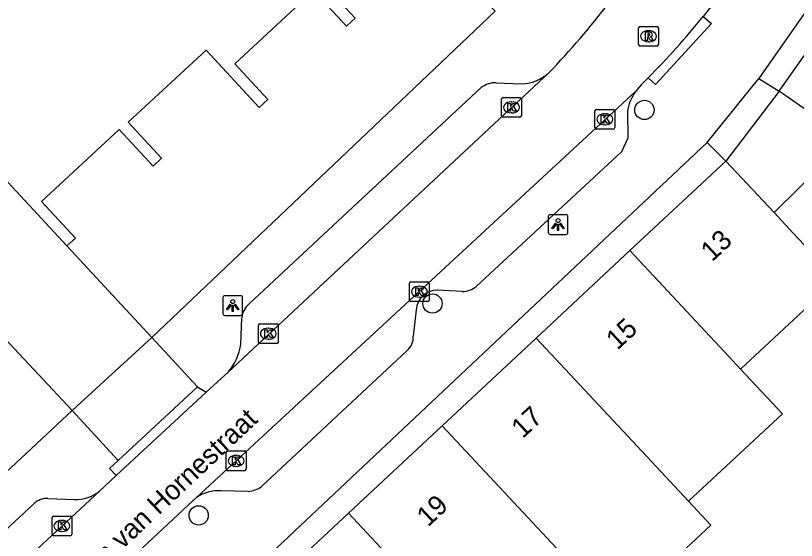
# Model space of a CAD drawing. Extents: x 161801 to 162379, y 382315 to 382832.
# Drawn here: x 161918.18 to 161957.74, y 382686.7 to 382713.31 of the extents above; entities that cross this region are included whole.
import ezdxf

# ---------------------------------------------------------------- set-up
doc = ezdxf.new("R2010")
doc.units = 0
for name, color, linetype in [('IMGEO_Boom', 7, 'Continuous'), ('IMGEO_Kolk', 7, 'Continuous'), ('IMGEO_Lichtpunt', 7, 'Continuous'), ('IMGEO_Openbare_ruimte_label', 7, 'Continuous'), ('IMGEO_Pand', 7, 'Continuous'), ('IMGEO_Pand_nummerreeks', 7, 'Continuous'), ('IMGEO_Pand_overbouw', 7, 'Continuous'), ('IMGEO_Rijbaan_lokaal_open', 7, 'Continuous'), ('IMGEO_Rioolput', 7, 'Continuous'), ('IMGEO_Voetpad_open', 7, 'Continuous')]:
    doc.layers.add(name, color=color, linetype=linetype)

msp = doc.modelspace()

# ---------------------------------------------------------------- linework, layer by layer
at = {"layer": 'IMGEO_Boom'}
for centre in [(161950.038, 382708.52), (161939.3, 382698.705), (161927.456, 382687.964)]:
    msp.add_circle(centre, 0.489, dxfattribs=at)
at = {"layer": 'IMGEO_Kolk'}
for p, q in [((161942.805, 382708.227), (161942.805, 382709.079)), ((161942.88, 382709.153), (161943.732, 382709.153)), ((161943.806, 382709.079), (161943.806, 382708.227)), ((161943.293, 382708.933), (161943.318, 382708.933)), ((161943.316, 382708.373), (161943.291, 382708.373)), ((161947.532, 382707.624), (161947.532, 382708.476)), ((161947.607, 382708.55), (161948.459, 382708.55)), ((161948.02, 382708.33), (161948.045, 382708.33)), ((161948.533, 382708.476), (161948.533, 382707.624)), ((161943.732, 382708.153), (161942.88, 382708.153)), ((161948.459, 382707.55), (161947.607, 382707.55)), ((161948.043, 382707.77), (161948.018, 382707.77)), ((161938.135, 382698.881), (161938.135, 382699.733)), ((161938.21, 382699.807), (161939.062, 382699.807)), ((161938.623, 382699.587), (161938.648, 382699.587)), ((161939.136, 382699.733), (161939.136, 382698.881)), ((161939.062, 382698.807), (161938.21, 382698.807)), ((161938.646, 382699.027), (161938.621, 382699.027)), ((161930.558, 382697.677), (161931.41, 382697.677)), ((161930.483, 382696.751), (161930.483, 382697.603)), ((161930.971, 382697.457), (161930.996, 382697.457)), ((161931.484, 382697.603), (161931.484, 382696.751)), ((161930.994, 382696.897), (161930.969, 382696.897)), ((161931.41, 382696.677), (161930.558, 382696.677)), ((161928.854, 382690.303), (161928.854, 382691.155)), ((161928.929, 382691.229), (161929.781, 382691.229)), ((161929.342, 382691.009), (161929.367, 382691.009)), ((161929.855, 382691.155), (161929.855, 382690.303)), ((161929.781, 382690.229), (161928.929, 382690.229)), ((161929.365, 382690.449), (161929.34, 382690.449)), ((161920.026, 382687.006), (161920.026, 382687.858)), ((161920.101, 382687.932), (161920.953, 382687.932)), ((161921.027, 382687.858), (161921.027, 382687.006)), ((161920.514, 382687.712), (161920.539, 382687.712)), ((161920.953, 382686.932), (161920.101, 382686.932)), ((161920.537, 382687.152), (161920.512, 382687.152))]:
    msp.add_line(p, q, dxfattribs=at)
for points in [[(161942.805, 382708.227), (161942.805, 382709.079)], [(161942.88, 382709.153), (161943.732, 382709.153)], [(161943.806, 382709.079), (161943.806, 382708.227)], [(161943.126, 382708.853), (161943.249, 382708.853), (161943.249, 382708.702), (161943.379, 382708.853), (161943.543, 382708.853), (161943.397, 382708.702), (161943.55, 382708.453), (161943.398, 382708.453), (161943.313, 382708.617), (161943.249, 382708.55), (161943.249, 382708.453), (161943.126, 382708.453), (161943.126, 382708.853)], [(161947.532, 382707.624), (161947.532, 382708.476)], [(161947.607, 382708.55), (161948.459, 382708.55)], [(161948.533, 382708.476), (161948.533, 382707.624)], [(161943.732, 382708.153), (161942.88, 382708.153)], [(161947.853, 382708.25), (161947.976, 382708.25), (161947.976, 382708.099), (161948.106, 382708.25), (161948.27, 382708.25), (161948.124, 382708.099), (161948.277, 382707.85), (161948.125, 382707.85), (161948.04, 382708.014), (161947.976, 382707.947), (161947.976, 382707.85), (161947.853, 382707.85), (161947.853, 382708.25)], [(161948.459, 382707.55), (161947.607, 382707.55)], [(161938.135, 382698.881), (161938.135, 382699.733)], [(161938.21, 382699.807), (161939.062, 382699.807)], [(161939.136, 382699.733), (161939.136, 382698.881)], [(161938.456, 382699.507), (161938.579, 382699.507), (161938.579, 382699.356), (161938.709, 382699.507), (161938.873, 382699.507), (161938.727, 382699.356), (161938.88, 382699.107), (161938.728, 382699.107), (161938.643, 382699.271), (161938.579, 382699.204), (161938.579, 382699.107), (161938.456, 382699.107), (161938.456, 382699.507)], [(161939.062, 382698.807), (161938.21, 382698.807)], [(161930.558, 382697.677), (161931.41, 382697.677)], [(161930.483, 382696.751), (161930.483, 382697.603)], [(161930.804, 382697.377), (161930.927, 382697.377), (161930.927, 382697.226), (161931.057, 382697.377), (161931.221, 382697.377), (161931.075, 382697.226), (161931.228, 382696.977), (161931.076, 382696.977), (161930.991, 382697.141), (161930.927, 382697.074), (161930.927, 382696.977), (161930.804, 382696.977), (161930.804, 382697.377)], [(161931.484, 382697.603), (161931.484, 382696.751)], [(161931.41, 382696.677), (161930.558, 382696.677)], [(161928.854, 382690.303), (161928.854, 382691.155)], [(161928.929, 382691.229), (161929.781, 382691.229)], [(161929.175, 382690.929), (161929.298, 382690.929), (161929.298, 382690.778), (161929.428, 382690.929), (161929.592, 382690.929), (161929.446, 382690.778), (161929.599, 382690.529), (161929.447, 382690.529), (161929.362, 382690.693), (161929.298, 382690.626), (161929.298, 382690.529), (161929.175, 382690.529), (161929.175, 382690.929)], [(161929.855, 382691.155), (161929.855, 382690.303)], [(161929.781, 382690.229), (161928.929, 382690.229)], [(161920.026, 382687.006), (161920.026, 382687.858)], [(161920.101, 382687.932), (161920.953, 382687.932)], [(161921.027, 382687.858), (161921.027, 382687.006)], [(161920.347, 382687.632), (161920.47, 382687.632), (161920.47, 382687.481), (161920.6, 382687.632), (161920.764, 382687.632), (161920.618, 382687.481), (161920.771, 382687.232), (161920.619, 382687.232), (161920.534, 382687.396), (161920.47, 382687.329), (161920.47, 382687.232), (161920.347, 382687.232), (161920.347, 382687.632)], [(161920.953, 382686.932), (161920.101, 382686.932)]]:
    msp.add_lwpolyline(points, dxfattribs=at)
for centre, start, end in [((161942.882, 382709.077), 91.552, 178.448), ((161942.882, 382709.077), 91.552, 178.448), ((161943.73, 382709.077), 1.552, 88.448), ((161943.73, 382709.077), 1.552, 88.448), ((161947.609, 382708.474), 91.552, 178.448), ((161947.609, 382708.474), 91.552, 178.448), ((161948.457, 382708.474), 1.552, 88.448), ((161948.457, 382708.474), 1.552, 88.448), ((161942.882, 382708.229), 181.552, 268.448), ((161942.882, 382708.229), 181.552, 268.448), ((161943.73, 382708.229), 271.552, 358.448), ((161943.73, 382708.229), 271.552, 358.448), ((161947.609, 382707.626), 181.552, 268.448), ((161947.609, 382707.626), 181.552, 268.448), ((161948.457, 382707.626), 271.552, 358.448), ((161948.457, 382707.626), 271.552, 358.448), ((161938.212, 382699.731), 91.552, 178.448), ((161938.212, 382699.731), 91.552, 178.448), ((161939.06, 382699.731), 1.552, 88.448), ((161939.06, 382699.731), 1.552, 88.448), ((161938.212, 382698.883), 181.552, 268.448), ((161938.212, 382698.883), 181.552, 268.448), ((161939.06, 382698.883), 271.552, 358.448), ((161939.06, 382698.883), 271.552, 358.448), ((161930.56, 382697.601), 91.552, 178.448), ((161930.56, 382697.601), 91.552, 178.448), ((161931.408, 382697.601), 1.552, 88.448), ((161931.408, 382697.601), 1.552, 88.448), ((161930.56, 382696.753), 181.552, 268.448), ((161930.56, 382696.753), 181.552, 268.448), ((161931.408, 382696.753), 271.552, 358.448), ((161931.408, 382696.753), 271.552, 358.448), ((161928.931, 382691.153), 91.552, 178.448), ((161928.931, 382691.153), 91.552, 178.448), ((161929.779, 382691.153), 1.552, 88.448), ((161929.779, 382691.153), 1.552, 88.448), ((161928.931, 382690.305), 181.552, 268.448), ((161928.931, 382690.305), 181.552, 268.448), ((161929.779, 382690.305), 271.552, 358.448), ((161929.779, 382690.305), 271.552, 358.448), ((161920.103, 382687.856), 91.552, 178.448), ((161920.103, 382687.856), 91.552, 178.448), ((161920.951, 382687.856), 1.552, 88.448), ((161920.951, 382687.856), 1.552, 88.448), ((161920.103, 382687.008), 181.552, 268.448), ((161920.103, 382687.008), 181.552, 268.448), ((161920.951, 382687.008), 271.552, 358.448), ((161920.951, 382687.008), 271.552, 358.448)]:
    msp.add_arc(centre, 0.0765, start, end, dxfattribs=at)
for centre, major_axis, ratio, start_param, end_param in [((161943.292, 382708.653), (-0.387, 0.002), 0.722429, 4.712389, 7.853982), ((161943.317, 382708.653), (-0.39, 0.002), 0.717154, 1.570796, 4.712389), ((161948.019, 382708.05), (-0.387, 0.002), 0.722429, 4.712389, 7.853982), ((161948.044, 382708.05), (-0.39, 0.002), 0.717154, 1.570796, 4.712389), ((161938.622, 382699.307), (-0.387, 0.002), 0.722429, 4.712389, 7.853982), ((161938.647, 382699.307), (-0.39, 0.002), 0.717154, 1.570796, 4.712389), ((161930.97, 382697.177), (-0.387, 0.002), 0.722429, 4.712389, 7.853982), ((161930.995, 382697.177), (-0.39, 0.002), 0.717154, 1.570796, 4.712389), ((161929.341, 382690.729), (-0.387, 0.002), 0.722429, 4.712389, 7.853982), ((161929.366, 382690.729), (-0.39, 0.002), 0.717154, 1.570796, 4.712389), ((161920.513, 382687.432), (-0.387, 0.002), 0.722429, 4.712389, 7.853982), ((161920.538, 382687.432), (-0.39, 0.002), 0.717154, 1.570796, 4.712389)]:
    msp.add_ellipse(centre, major_axis=major_axis, ratio=ratio, start_param=start_param, end_param=end_param, dxfattribs=at)
at = {"layer": 'IMGEO_Lichtpunt'}
for p, q in [((161946.068, 382703.208), (161945.26, 382703.208)), ((161946.068, 382703.208), (161945.26, 382703.208)), ((161945.166, 382703.113), (161945.166, 382702.306)), ((161945.166, 382703.113), (161945.166, 382702.306)), ((161946.162, 382702.306), (161946.162, 382703.113)), ((161946.162, 382702.306), (161946.162, 382703.113)), ((161945.26, 382702.212), (161946.068, 382702.212)), ((161945.26, 382702.212), (161946.068, 382702.212)), ((161928.684, 382699.006), (161928.684, 382698.199)), ((161928.684, 382699.006), (161928.684, 382698.199)), ((161929.586, 382699.101), (161928.778, 382699.101)), ((161929.586, 382699.101), (161928.778, 382699.101)), ((161929.68, 382698.199), (161929.68, 382699.006)), ((161929.68, 382698.199), (161929.68, 382699.006)), ((161928.778, 382698.105), (161929.586, 382698.105)), ((161928.778, 382698.105), (161929.586, 382698.105))]:
    msp.add_line(p, q, dxfattribs=at)
for points in [[(161945.54, 382702.777), (161945.579, 382702.749), (161945.391, 382702.487), (161945.353, 382702.514), (161945.54, 382702.777)], [(161945.752, 382702.749), (161945.79, 382702.776), (161945.977, 382702.514), (161945.938, 382702.486), (161945.752, 382702.749)], [(161945.642, 382702.729), (161945.689, 382702.729), (161945.689, 382702.407), (161945.642, 382702.407), (161945.642, 382702.729)], [(161929.058, 382698.67), (161929.097, 382698.642), (161928.909, 382698.38), (161928.871, 382698.407), (161929.058, 382698.67)], [(161929.16, 382698.622), (161929.207, 382698.622), (161929.207, 382698.3), (161929.16, 382698.3), (161929.16, 382698.622)], [(161929.27, 382698.642), (161929.308, 382698.669), (161929.495, 382698.407), (161929.456, 382698.379), (161929.27, 382698.642)]]:
    msp.add_lwpolyline(points, dxfattribs=at)
for centre in [(161945.665, 382702.911), (161929.183, 382698.804)]:
    msp.add_circle(centre, 0.0994, dxfattribs=at)
for centre, start, end in [((161945.26, 382703.113), 90, 180), ((161945.26, 382703.113), 90, 180), ((161946.068, 382703.113), 0, 90), ((161946.068, 382703.113), 0, 90), ((161945.26, 382702.306), 180, 270), ((161945.26, 382702.306), 180, 270), ((161946.068, 382702.306), 270, 0), ((161946.068, 382702.306), 270, 360), ((161928.778, 382699.006), 90, 180), ((161928.778, 382699.006), 90, 180), ((161929.586, 382699.006), 0, 90), ((161929.586, 382699.006), 0, 90), ((161928.778, 382698.199), 180, 270), ((161928.778, 382698.199), 180, 270), ((161929.586, 382698.199), 270, 0), ((161929.586, 382698.199), 270, 360)]:
    msp.add_arc(centre, 0.0946, start, end, dxfattribs=at)
at = {"layer": 'IMGEO_Pand'}
for points in [[(161939.315, 382716.857), (161937.63, 382718.675), (161933.68, 382715.013), (161935.385, 382713.173), (161934.95, 382712.77), (161933.281, 382714.571), (161929.281, 382710.864), (161930.963, 382709.05), (161930.526, 382708.645), (161927.829, 382711.555), (161923.886, 382707.901), (161925.58, 382706.073), (161925.148, 382705.673), (161923.428, 382707.528), (161919.49, 382703.878), (161921.21, 382702.023), (161920.781, 382701.625)], [(161956.87, 382709.475), (161960.71, 382714.946)], [(161920.781, 382701.625), (161909.25, 382714.065)], [(161967.445, 382710.219), (161963.599, 382704.753), (161960.963, 382706.603), (161960.358, 382707.027), (161956.87, 382709.475)], [(161954.163, 382705.932), (161949.3, 382701.389)], [(161954.163, 382705.932), (161956.607, 382703.318), (161957.577, 382702.279), (161959.782, 382699.919), (161954.912, 382695.382)], [(161949.3, 382701.389), (161944.547, 382696.948)], [(161949.3, 382701.389), (161954.31, 382696.027), (161954.912, 382695.382)], [(161914.601, 382700.2), (161917.642, 382696.935), (161921.051, 382693.277)], [(161944.547, 382696.948), (161939.794, 382692.509)], [(161944.547, 382696.948), (161950.153, 382690.948), (161952.27, 382688.682)], [(161954.912, 382695.382), (161957.03, 382693.115), (161952.27, 382688.682)], [(161921.051, 382693.277), (161915.857, 382688.442)], [(161939.794, 382692.509), (161935.042, 382688.069)], [(161939.794, 382692.509), (161947.508, 382684.246)], [(161952.27, 382688.682), (161953.402, 382687.471), (161948.647, 382683.03), (161947.508, 382684.246)], [(161935.042, 382688.069), (161930.18, 382683.527)], [(161935.042, 382688.069), (161940.635, 382682.08)]]:
    msp.add_lwpolyline(points, dxfattribs=at)
at = {"layer": 'IMGEO_Pand_overbouw'}
for points in [[(161954.163, 382705.932), (161956.607, 382703.318), (161960.358, 382707.027), (161956.87, 382709.475)], [(161963.599, 382704.753), (161960.963, 382706.603), (161960.358, 382707.027), (161956.607, 382703.318), (161957.577, 382702.279), (161959.782, 382699.919)]]:
    msp.add_lwpolyline(points, close=True, dxfattribs=at)
at = {"layer": 'IMGEO_Rijbaan_lokaal_open'}
for points in [[(161954.232, 382714.711), (161954.011, 382714.515), (161953.841, 382714.33), (161953.014, 382713.254)], [(161928.944, 382695.23), (161945.213, 382710.416)], [(161950.225, 382710.144), (161949.878, 382709.799), (161949.605, 382709.468)], [(161949.605, 382709.468), (161927.342, 382688.871)], [(161925.083, 382696.984), (161922.903, 382699.334), (161920.781, 382701.625)], [(161921.051, 382693.277), (161925.083, 382696.984)], [(161927.839, 382694.207), (161928.944, 382695.23)], [(161923.279, 382689.986), (161927.839, 382694.207)], [(161922.425, 382689.194), (161923.279, 382689.986)], [(161899.049, 382666.462), (161900.203, 382668.529), (161922.425, 382689.194)], [(161927.342, 382688.871), (161927.173, 382688.715), (161922.04, 382683.924)]]:
    msp.add_lwpolyline(points, dxfattribs=at)
for centre, radius, start, end in [((161913.61, 382740.517), 43.644, 316.3953, 328.6224), ((161920.867, 382739.277), 41.359, 315.22, 321.0095)]:
    msp.add_arc(centre, radius, start, end, dxfattribs=at)
at = {"layer": 'IMGEO_Rioolput'}
for p, q in [((161949.743, 382711.833), (161949.743, 382712.685)), ((161949.818, 382712.759), (161950.67, 382712.759)), ((161950.744, 382712.685), (161950.744, 382711.833)), ((161950.231, 382712.539), (161950.256, 382712.539)), ((161950.254, 382711.979), (161950.229, 382711.979)), ((161950.67, 382711.759), (161949.818, 382711.759))]:
    msp.add_line(p, q, dxfattribs=at)
for points in [[(161949.743, 382711.833), (161949.743, 382712.685)], [(161949.818, 382712.759), (161950.67, 382712.759)], [(161950.744, 382712.685), (161950.744, 382711.833)], [(161950.332, 382712.457), (161950.08, 382712.459), (161950.08, 382712.059)], [(161950.258, 382712.378), (161950.204, 382712.378), (161950.204, 382712.297)], [(161950.204, 382712.297), (161950.256, 382712.297)], [(161950.08, 382712.059), (161950.204, 382712.059), (161950.204, 382712.221), (161950.215, 382712.221)], [(161950.262, 382712.192), (161950.333, 382712.059), (161950.473, 382712.059), (161950.408, 382712.185)], [(161950.67, 382711.759), (161949.818, 382711.759)]]:
    msp.add_lwpolyline(points, dxfattribs=at)
for centre, radius, start, end in [((161949.82, 382712.683), 0.0765, 91.552, 178.448), ((161949.82, 382712.683), 0.0765, 91.552, 178.448), ((161950.668, 382712.683), 0.0765, 1.552, 88.448), ((161950.668, 382712.683), 0.0765, 1.552, 88.448), ((161950.24, 382712.486), 0.19, 274.7715, 282.9687), ((161950.264, 382712.282), 0.0964, 77.0061, 93.1865), ((161950.278, 382712.339), 0.0378, 276.6634, 79.6772), ((161950.331, 382712.347), 0.109, 350.3612, 89.416), ((161950.329, 382712.347), 0.112, 277.5842, 350.9817), ((161950.214, 382712.168), 0.0533, 26.0293, 88.6989), ((161950.313, 382712.132), 0.108, 29.5134, 73.7905), ((161949.82, 382711.835), 0.0765, 181.552, 268.448), ((161949.82, 382711.835), 0.0765, 181.552, 268.448), ((161950.668, 382711.835), 0.0765, 271.552, 358.448), ((161950.668, 382711.835), 0.0765, 271.552, 358.448)]:
    msp.add_arc(centre, radius, start, end, dxfattribs=at)
for centre, major_axis, ratio, start_param, end_param in [((161950.23, 382712.259), (-0.387, 0.002), 0.722429, 4.712389, 7.853982), ((161950.255, 382712.259), (-0.39, 0.002), 0.717154, 1.570796, 4.712389)]:
    msp.add_ellipse(centre, major_axis=major_axis, ratio=ratio, start_param=start_param, end_param=end_param, dxfattribs=at)
at = {"layer": 'IMGEO_Voetpad_open'}
for points in [[(161981.747, 382747.198), (161955.826, 382710.123)], [(161941.286, 382714.73), (161942.474, 382713.523), (161925.083, 382696.984)], [(161953.014, 382713.254), (161953.428, 382712.907), (161950.594, 382709.807), (161950.225, 382710.144)], [(161942.527, 382709.898), (161943.778, 382709.843)], [(161953.212, 382706.879), (161955.826, 382710.123)], [(161955.826, 382710.123), (161956.87, 382709.475)], [(161930.01, 382698.684), (161941.775, 382709.657)], [(161956.87, 382709.475), (161954.163, 382705.932)], [(161949.183, 382708.413), (161949.204, 382707.096), (161948.881, 382706.405), (161941.515, 382699.562)], [(161929.388, 382684.409), (161953.212, 382706.879)], [(161953.212, 382706.879), (161954.163, 382705.932)], [(161940.813, 382699.31), (161939.537, 382699.376)], [(161938.469, 382698.387), (161938.32, 382697.048)], [(161929.584, 382696.649), (161929.638, 382697.984)], [(161925.083, 382696.984), (161927.394, 382694.49)], [(161938.012, 382696.323), (161930.643, 382689.435)], [(161927.394, 382694.49), (161923.384, 382690.753)], [(161927.394, 382694.49), (161927.839, 382694.207)], [(161923.384, 382690.753), (161921.051, 382693.277)], [(161923.279, 382689.986), (161922.945, 382690.344), (161923.384, 382690.753)], [(161929.963, 382689.175), (161928.588, 382689.208)], [(161899.069, 382667.689), (161898.728, 382669.061), (161898.946, 382669.761), (161919.116, 382688.561)], [(161919.812, 382688.826), (161921.172, 382688.763)]]:
    msp.add_lwpolyline(points, dxfattribs=at)
for centre, radius, start, end in [((161943.735, 382712.035), 2.192, 271.1294, 312.4045), ((161942.486, 382708.731), 1.168, 88.005, 127.5341), ((161951.238, 382708.203), 2.066, 142.2348, 174.1624), ((161939.522, 382698.321), 1.055, 89.1893, 176.4119), ((161940.756, 382700.572), 1.263, 272.5762, 306.9175), ((161930.731, 382697.852), 1.101, 130.911, 173.1141), ((161937.496, 382696.97), 0.828, 308.5641, 5.4017), ((161926.967, 382696.975), 2.637, 318.557, 352.8902), ((161929.888, 382690.39), 1.217, 273.5206, 308.3284), ((161921.224, 382690.649), 1.886, 268.4197, 309.5442), ((161928.453, 382687.233), 1.979, 86.1024, 124.1665), ((161919.782, 382687.859), 0.967, 88.1993, 133.4891)]:
    msp.add_arc(centre, radius, start, end, dxfattribs=at)

# ---------------------------------------------------------------- texts
at = {"layer": 'IMGEO_Openbare_ruimte_label'}
msp.add_text('Willem van Hornestraat', height=1, rotation=43.3796, dxfattribs=at).set_placement((161920.407, 382683.202))
at = {"layer": 'IMGEO_Pand_nummerreeks'}
for s, rotation, p in [('13', 43.052, (161953.466, 382700.793)), ('15', 43.052, (161948.67, 382696.312)), ('17', 43.052, (161943.873, 382691.831)), ('19', 43.0517, (161939.077, 382687.35))]:
    msp.add_text(s, height=1, rotation=rotation, dxfattribs=at).set_placement(p)

doc.saveas('drawing.dxf')
